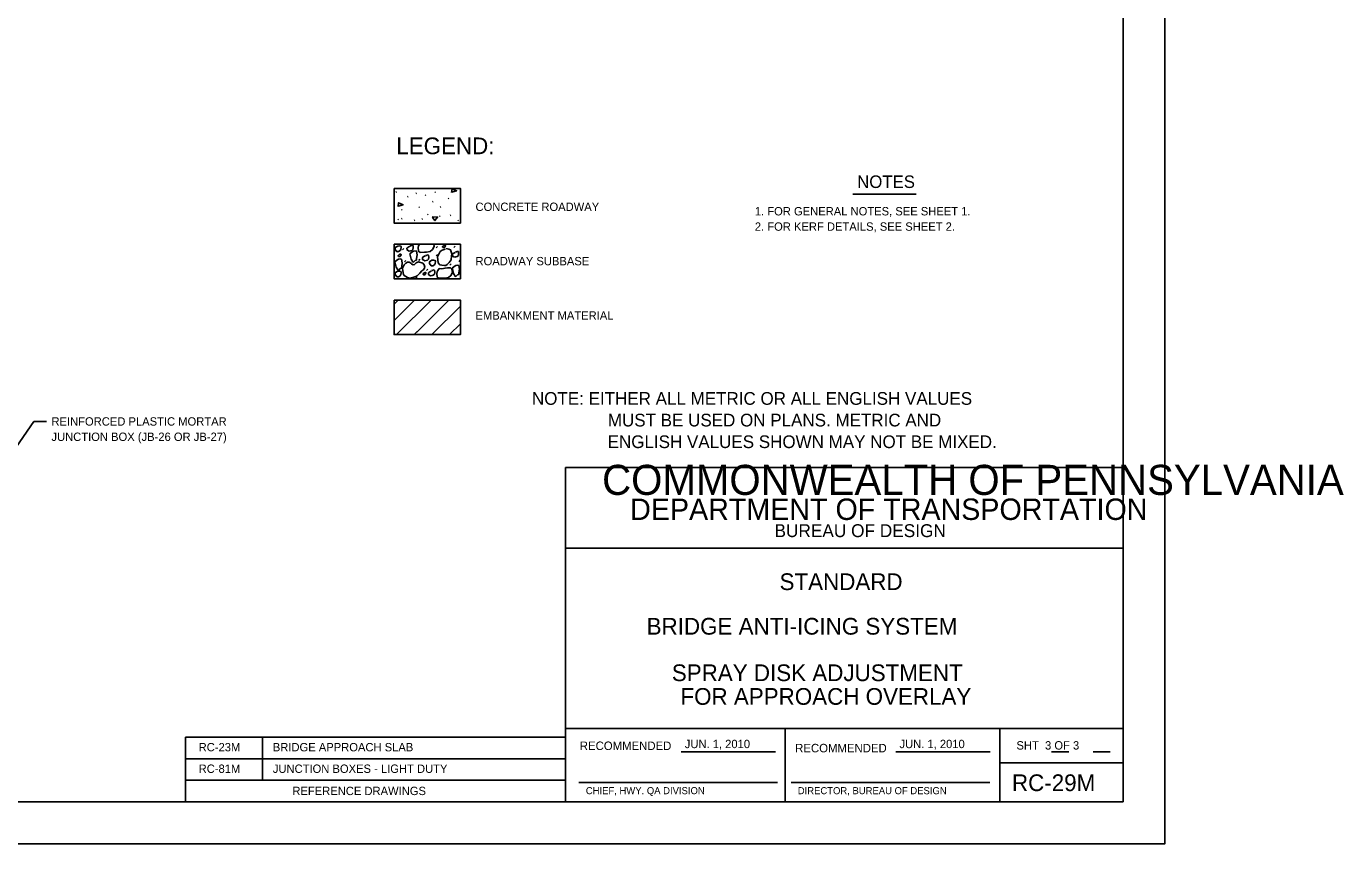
# Model space of a CAD drawing. Extents: x 3239 to 4230, y -4276 to -2494.
# Drawn here: x 3671.7 to 4144.1, y -4276.3 to -3983 of the extents above; entities that cross this region are included whole.
import ezdxf

# ---------------------------------------------------------------- set-up
doc = ezdxf.new("R2010")
doc.units = 0
for name, color, linetype in [('1', 7, 'Continuous'), ('2', 7, 'Continuous'), ('40', 7, 'Continuous'), ('PLT-BNDY', 7, 'Continuous')]:
    doc.layers.add(name, color=color, linetype=linetype)

msp = doc.modelspace()

# ---------------------------------------------------------------- linework, layer by layer
at = {"layer": '1'}
for p, q in [((4065.03, -4141.29), (3865.03, -4141.29)), ((3865.03, -4141.29), (3865.03, -4261.29)), ((3865.03, -4234.93), (3865.03, -4170.25)), ((3865.03, -4170.25), (4065.03, -4170.25)), ((4065.03, -4234.93), (3865.03, -4234.93)), ((3943.83, -4261.29), (3943.83, -4234.93)), ((3943.83, -4234.93), (3943.83, -4261.29)), ((4020.83, -4261.29), (4020.83, -4234.93)), ((4020.83, -4234.93), (4020.83, -4247.25)), ((3906.49, -4243.3), (3940.38, -4243.3)), ((3983.49, -4243.3), (4017.36, -4243.3)), ((4020.83, -4247.25), (4065.03, -4247.25)), ((4039.41, -4243.33), (4045.55, -4243.33)), ((4054.27, -4243.33), (4060.43, -4243.33)), ((3869.79, -4254.29), (3941.04, -4254.29)), ((3945.96, -4254.29), (4017.3, -4254.29))]:
    msp.add_line(p, q, dxfattribs=at)
at = {"layer": '2'}
for p, q in [((4065.03, -3697.29), (4065.03, -4261.29)), ((3804.26, -4042.56), (3804.49, -4042.37)), ((3808.37, -4044.23), (3808.6, -4044.04)), ((3811.36, -4043.04), (3811.59, -4042.85)), ((3814.71, -4043.74), (3814.94, -4043.55)), ((3818.24, -4042.63), (3818.47, -4042.45)), ((3968.15, -4043.27), (3990.83, -4043.27)), ((3806.25, -4048.96), (3806.48, -4048.77)), ((3812.46, -4048.04), (3812.69, -4047.85)), ((3817.33, -4046.06), (3817.56, -4045.87)), ((3820.13, -4047.94), (3820.36, -4047.76)), ((3822.94, -4044.92), (3823.18, -4044.73)), ((3804.95, -4052.41), (3805.18, -4052.22)), ((3806.2, -4052.13), (3806.44, -4051.94)), ((3810.78, -4052.76), (3811.02, -4052.57)), ((3813.58, -4052.26), (3813.82, -4052.08)), ((3815.58, -4050.62), (3815.81, -4050.43)), ((3819.87, -4051.21), (3820.1, -4051.02)), ((3823.64, -4050.93), (3823.88, -4050.74)), ((3826.38, -4052.77), (3826.62, -4052.58)), ((3803.59, -4088.57), (3810.93, -4081.24)), ((3803.59, -4082.72), (3805.08, -4081.24)), ((3804.42, -4093.64), (3816.83, -4081.24)), ((3811.72, -4092.71), (3823.19, -4081.24)), ((3817.15, -4093.64), (3827.34, -4083.45)), ((3823.51, -4093.64), (3827.34, -4089.82)), ((3810.79, -4093.64), (3811.89, -4092.54)), ((3728.73, -4238.08), (3728.73, -4261.29)), ((3865.03, -4238.08), (3728.73, -4238.08)), ((3756.39, -4238.08), (3756.39, -4253.55)), ((3865.03, -4245.82), (3728.73, -4245.82)), ((3728.73, -4245.82), (3728.73, -4261.29)), ((3865.03, -4245.82), (3728.73, -4245.82)), ((3756.39, -4245.82), (3756.39, -4253.55)), ((3865.03, -4253.55), (3728.73, -4253.55)), ((3865.03, -4253.55), (3728.73, -4253.55)), ((4065.03, -4261.29), (3279.03, -4261.29))]:
    msp.add_line(p, q, dxfattribs=at)
for points in [[(3803.59, -4041.21), (3827.34, -4041.21), (3827.34, -4053.62), (3803.59, -4053.62)], [(3803.59, -4061.23), (3827.34, -4061.23), (3827.34, -4073.63), (3803.59, -4073.63)], [(3803.59, -4081.24), (3827.34, -4081.24), (3827.34, -4093.64), (3803.59, -4093.64)]]:
    msp.add_lwpolyline(points, close=True, dxfattribs=at)
for points in [[(3824.22, -4042.65), (3824.36, -4041.3), (3825.99, -4042.05), (3824.34, -4042.54)], [(3805.02, -4047.68), (3805.16, -4046.33), (3806.79, -4047.07), (3805.13, -4047.56)], [(3817.27, -4051.44), (3819.2, -4051.46), (3818.22, -4052.72), (3817.41, -4051.58)], [(3805.62, -4061.84), (3804.86, -4061.91), (3804.42, -4062.1), (3804.02, -4062.44), (3803.92, -4063.06), (3804.58, -4063.9), (3804.88, -4063.87), (3805.19, -4063.84), (3805.77, -4063.51), (3805.91, -4063.34), (3806.03, -4063.03), (3806.13, -4062.41), (3806.1, -4062.11), (3805.94, -4061.97), (3805.77, -4061.83)], [(3807.05, -4062.77), (3806.63, -4063.26)], [(3809.19, -4061.97), (3808.46, -4062.34), (3808.18, -4062.67), (3808.24, -4063.28), (3808.72, -4063.54), (3809.03, -4063.67), (3809.49, -4063.63), (3809.93, -4063.43), (3810.33, -4063.09), (3810.43, -4062.48), (3810.37, -4061.72), (3809.92, -4061.6), (3809.63, -4061.78), (3809.33, -4061.81)], [(3812.67, -4061.23), (3812.64, -4061.27), (3812.37, -4061.75), (3812.27, -4062.35), (3812.39, -4063.71), (3812.89, -4064.13), (3814.54, -4064.11), (3815.15, -4064.06), (3816.48, -4063.81), (3817.33, -4063.13), (3817.97, -4062), (3817.81, -4061.23)], [(3819.1, -4062.07), (3818.68, -4062.56)], [(3821.88, -4062.95), (3820.86, -4063.34), (3820.15, -4063.84), (3819.48, -4064.97), (3819.09, -4065.76), (3819.43, -4067.85), (3819.95, -4068.56), (3820.73, -4068.78), (3821.63, -4068.85), (3822.08, -4068.81), (3822.66, -4068.46), (3823.37, -4067.81), (3824.02, -4066.83), (3824.21, -4065.47), (3824.29, -4064.7), (3823.86, -4063.23), (3823.25, -4062.98), (3822.78, -4062.87), (3822.17, -4062.77)], [(3825.47, -4061.89), (3825.06, -4062.39)], [(3805.94, -4066.47), (3805.18, -4066.53), (3804.61, -4066.89), (3803.9, -4067.56), (3804.13, -4068.44), (3804.37, -4069.48), (3804.91, -4070.35), (3805.22, -4070.48), (3805.79, -4069.97), (3806.23, -4069.78), (3806.31, -4069.16), (3806.51, -4067.94), (3806.24, -4066.6), (3806.07, -4066.46)], [(3810.44, -4068.65), (3809.96, -4068.38), (3809.78, -4068.09), (3809, -4067.71), (3808.39, -4067.61), (3807.81, -4067.96), (3807.25, -4068.62), (3806.61, -4069.75), (3806.7, -4070.78), (3806.97, -4072.13), (3807.15, -4072.4), (3808.42, -4073.2), (3809.5, -4073.42), (3810.67, -4073.01), (3811.41, -4072.79), (3811.85, -4072.6), (3812.81, -4071.62), (3813.5, -4070.8), (3814.22, -4070.28), (3814.59, -4069.48), (3814.36, -4068.61), (3813.87, -4068.04), (3812.3, -4067.57), (3811.44, -4067.95), (3810.74, -4068.62), (3810.59, -4068.63)], [(3807.75, -4067.04), (3807.33, -4067.54)], [(3811.29, -4063.6), (3810.53, -4063.67), (3809.95, -4064.03), (3809.25, -4064.7), (3809.48, -4065.57), (3809.72, -4066.62), (3810.25, -4067.49), (3810.57, -4067.61), (3811.14, -4067.1), (3811.58, -4066.91), (3811.65, -4066.3), (3811.85, -4065.08), (3811.58, -4063.73), (3811.42, -4063.59)], [(3812.84, -4066.57), (3812.42, -4067.07)], [(3814.76, -4065.43), (3814.03, -4065.79), (3813.75, -4066.12), (3813.8, -4066.73), (3814.29, -4066.99), (3814.6, -4067.12), (3815.06, -4067.08), (3815.5, -4066.89), (3815.9, -4066.54), (3816, -4065.93), (3815.93, -4065.17), (3815.49, -4065.06), (3815.2, -4065.23), (3814.9, -4065.26)], [(3817.92, -4066.91), (3817.16, -4066.97), (3816.72, -4067.16), (3816.31, -4067.5), (3816.22, -4068.12), (3816.88, -4068.96), (3817.18, -4068.93), (3817.48, -4068.91), (3818.06, -4068.57), (3818.2, -4068.41), (3818.33, -4068.09), (3818.42, -4067.47), (3818.4, -4067.17), (3818.23, -4067.03), (3818.07, -4066.89)], [(3819.1, -4064.88), (3818.68, -4065.37)], [(3825.48, -4064.14), (3824.75, -4064.51), (3824.48, -4064.84), (3824.53, -4065.44), (3825.01, -4065.71), (3825.33, -4065.83), (3825.78, -4065.79), (3826.22, -4065.6), (3826.63, -4065.26), (3826.73, -4064.64), (3826.66, -4063.88), (3826.21, -4063.77), (3825.92, -4063.95), (3825.62, -4063.98)], [(3827.28, -4066.98), (3826.87, -4067.48)], [(3805.62, -4070.86), (3804.86, -4070.92), (3804.42, -4071.11), (3804.02, -4071.45), (3803.92, -4072.07), (3804.58, -4072.91), (3804.88, -4072.88), (3805.19, -4072.86), (3805.77, -4072.52), (3805.91, -4072.36), (3806.03, -4072.04), (3806.13, -4071.42), (3806.1, -4071.12), (3805.94, -4070.98), (3805.77, -4070.84)], [(3815.63, -4070.14), (3815.21, -4070.63)], [(3816.89, -4070.83), (3816.16, -4071.2), (3815.89, -4071.53), (3815.94, -4072.13), (3816.42, -4072.4), (3816.74, -4072.52), (3817.19, -4072.48), (3817.63, -4072.29), (3818.04, -4071.95), (3818.14, -4071.33), (3818.07, -4070.57), (3817.62, -4070.46), (3817.33, -4070.64), (3817.03, -4070.67)], [(3820.68, -4070), (3819.76, -4069.93), (3819.23, -4070.59), (3818.97, -4071.07), (3818.87, -4071.67), (3818.99, -4073.03), (3819.48, -4073.44), (3821.14, -4073.43), (3821.74, -4073.38), (3823.07, -4073.13), (3823.93, -4072.44), (3824.57, -4071.32), (3824.31, -4070.15), (3823.84, -4069.73), (3822.77, -4069.67), (3821.86, -4069.75), (3821.29, -4069.95), (3820.68, -4070)], [(3824.01, -4068.27), (3823.59, -4068.76)], [(3826.48, -4068.73), (3825.72, -4068.8), (3825.14, -4069.16), (3824.44, -4069.83), (3824.67, -4070.7), (3824.91, -4071.75), (3825.44, -4072.62), (3825.76, -4072.74), (3826.33, -4072.23), (3826.77, -4072.04), (3826.84, -4071.43), (3827.04, -4070.21), (3826.77, -4068.86), (3826.61, -4068.72)], [(3811.75, -4073.01), (3811.34, -4073.51)], [(3668, -4133.99), (3674.42, -4124.84), (3678.96, -4124.84)]]:
    msp.add_lwpolyline(points, dxfattribs=at)
for points in [[(3821.92, -4061.98), (3821.85, -4062.18), (3821.69, -4062.34), (3821.26, -4062.45), (3821.01, -4062.29), (3820.92, -4062.04), (3821.19, -4061.86), (3821.69, -4061.6), (3822, -4061.64), (3821.92, -4062)], [(3806.02, -4065.21), (3805.95, -4065.41), (3805.79, -4065.58), (3805.36, -4065.68), (3805.11, -4065.53), (3805.02, -4065.28), (3805.29, -4065.1), (3805.79, -4064.84), (3806.1, -4064.88), (3806.02, -4065.23)], [(3814.93, -4071.72), (3814.86, -4071.92), (3814.7, -4072.09), (3814.28, -4072.19), (3814.03, -4072.04), (3813.94, -4071.79), (3814.2, -4071.61), (3814.71, -4071.35), (3815.01, -4071.39), (3814.94, -4071.74)]]:
    msp.add_spline(points, degree=3, dxfattribs=at)
at = {"layer": 'PLT-BNDY'}
msp.add_lwpolyline([(3239.03, -3682.29), (4080.03, -3682.29), (4080.03, -4276.29), (3239.03, -4276.29)], close=True, dxfattribs=at)

# ---------------------------------------------------------------- texts
at = {"layer": '1'}
for s, height, p in [('COMMONWEALTH OF PENNSYLVANIA', 10.7834, (3878.18, -4151.15)), ('DEPARTMENT OF TRANSPORTATION', 7.6843, (3888.24, -4160.14)), ('BUREAU OF DESIGN', 4.6221, (3940.01, -4166.3)), ('RECOMMENDED', 3.048, (3870.19, -4242.7)), ('JUN. 1, 2010', 3, (3907.83, -4242.01)), ('RECOMMENDED', 3.048, (3947.43, -4243.53)), ('JUN. 1, 2010', 3, (3984.83, -4242.01)), ('APPROVED', 0.0192, (3908.05, -4243.36)), ('CHIEF, HWY. QA DIVISION', 2.54, (3872.34, -4258.54)), ('DIRECTOR, BUREAU OF DESIGN', 2.54, (3948.36, -4258.55))]:
    msp.add_text(s, height=height, dxfattribs=at).set_placement(p)
at = {"layer": '2'}
for s, height, p in [('LEGEND:', 6, (3804.36, -4028.92)), ('NOTES', 4.5, (3969.66, -4041.04)), ('CONCRETE ROADWAY', 3, (3832.78, -4049.28)), ('1. FOR GENERAL NOTES, SEE SHEET 1.', 3, (3932.96, -4050.88)), ('2. FOR KERF DETAILS, SEE SHEET 2.', 3, (3932.96, -4056.38)), ('ROADWAY SUBBASE', 3, (3832.78, -4068.78)), ('EMBANKMENT MATERIAL', 3, (3832.78, -4088.28)), ('REINFORCED PLASTIC MORTAR ', 3, (3680.68, -4126.3)), ('JUNCTION BOX (JB-26 OR JB-27)', 3, (3680.68, -4131.8)), ('STANDARD', 6, (3941.83, -4185.3)), ('BRIDGE ANTI-ICING SYSTEM', 6, (3894.16, -4201.29)), ('SPRAY DISK ADJUSTMENT', 6, (3903.19, -4217.97)), ('FOR APPROACH OVERLAY', 6, (3906.28, -4226.47)), ('RC-23M', 3, (3733.48, -4243.17)), ('BRIDGE APPROACH SLAB', 3, (3760.08, -4243.17)), ('SHT  3 OF 3', 3, (4026.79, -4242.52)), ('RC-81M', 3, (3733.48, -4250.9)), ('JUNCTION BOXES - LIGHT DUTY', 3, (3760.08, -4250.9)), ('RC-29M', 6, (4025.19, -4257.43)), ('REFERENCE DRAWINGS', 3, (3767.09, -4258.86)), ('REFERENCE DRAWINGS', 3, (3767.09, -4258.86))]:
    msp.add_text(s, height=height, dxfattribs=at).set_placement(p)
at = {"layer": '40'}
for s, p in [('NOTE: EITHER ALL METRIC OR ALL ENGLISH VALUES', (3853.02, -4118.83)), ('MUST BE USED ON PLANS. METRIC AND', (3880.24, -4126.6)), ('ENGLISH VALUES SHOWN MAY NOT BE MIXED.', (3880.17, -4134.36))]:
    msp.add_text(s, height=4.5587, dxfattribs=at).set_placement(p)

doc.saveas('drawing.dxf')
